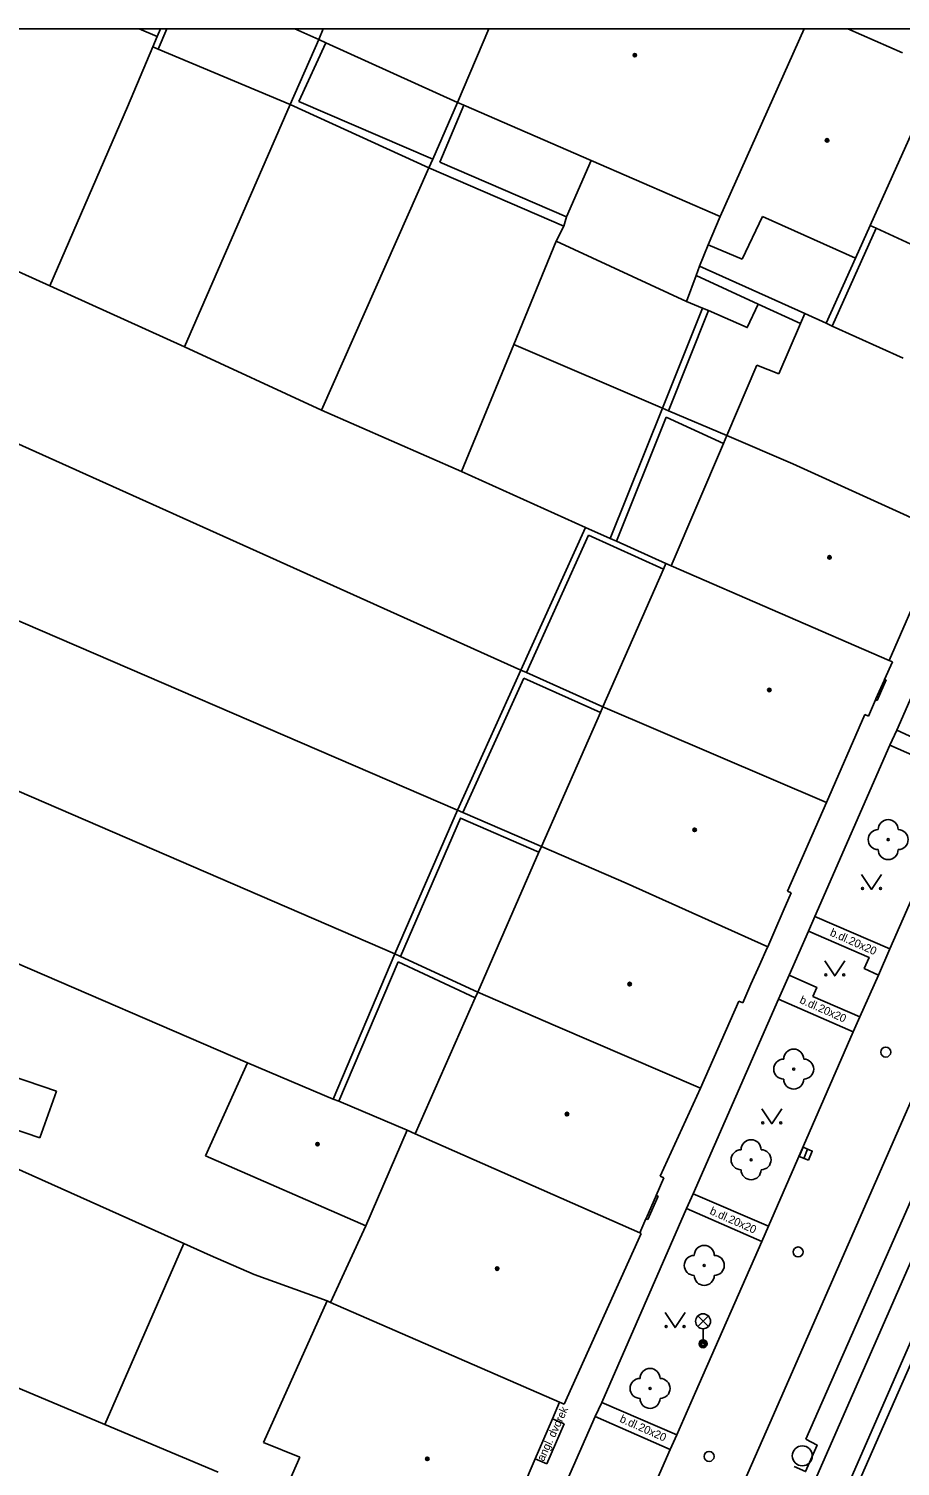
# Model space of a CAD drawing. Extents: x -596024 to -594475, y -1163820 to -1161957.
# Drawn here: x -595866.4 to -595822.8, y -1162028.7 to -1161956.9 of the extents above; entities that cross this region are included whole.
import ezdxf

# ---------------------------------------------------------------- set-up
doc = ezdxf.new("R2010")
doc.units = 0
for name, color, linetype in [('Level 10', 7, 'Continuous'), ('Level 11', 7, 'Continuous'), ('Level 22', 7, 'Continuous'), ('Level 27', 7, 'Continuous'), ('Level 28', 7, 'Continuous'), ('Level 33', 7, 'Continuous'), ('Level 36', 7, 'Continuous'), ('Level 39', 7, 'Continuous'), ('Level 40', 7, 'Continuous'), ('Level 42', 7, 'Continuous'), ('Level 5', 7, 'Continuous'), ('Level 6', 7, 'Continuous'), ('Level 7', 7, 'Continuous'), ('Vrstva 63', 7, 'Continuous')]:
    doc.layers.add(name, color=color, linetype=linetype)

msp = doc.modelspace()

# ---------------------------------------------------------------- linework, layer by layer
at = {"layer": 'Level 10'}
for points in [[(-595827.55, -1162027.38), (-595822.74, -1162016.44), (-595822.32, -1162015.5), (-595821.06, -1162012.53), (-595820.65, -1162011.59), (-595819.32, -1162008.66), (-595812.27, -1161992.6), (-595811.83, -1161991.6), (-595810.16, -1161987.8), (-595809.22, -1161985.63)], [(-595819.61, -1161994.34), (-595823.36, -1162002.87)], [(-595823.36, -1162002.87), (-595823.93, -1162004.18), (-595824.85, -1162006.27), (-595825.18, -1162007.02), (-595829.42, -1162016.73), (-595829.76, -1162017.5), (-595833.06, -1162025.03), (-595834, -1162027.16), (-595834.33, -1162027.9), (-595837.45, -1162035.01), (-595837.74, -1162035.66), (-595839.93, -1162040.66), (-595840.25, -1162041.39), (-595842.76, -1162047.12)], [(-595827.55, -1162027.38), (-595826.99, -1162027.67), (-595827.57, -1162029), (-595828.14, -1162028.75)]]:
    msp.add_lwpolyline(points, dxfattribs=at)
at = {"layer": 'Level 11'}
for p, q in [((-595860.866, -1161956.88), (-595859.97, -1161957.27)), ((-595859.491, -1161956.88), (-595859.93, -1161957.9))]:
    msp.add_line(p, q, dxfattribs=at)
for points in [[(-595859.97, -1161957.27), (-595860.19, -1161957.79)], [(-595859.81, -1161956.88), (-595859.97, -1161957.27)], [(-595851.9, -1161957.42), (-595853.33, -1161960.67)], [(-595860.19, -1161957.79), (-595861.45, -1161960.79), (-595865.34, -1161969.73)], [(-595859.93, -1161957.9), (-595860.19, -1161957.79)], [(-595853.33, -1161960.67), (-595859.93, -1161957.9)], [(-595852.89, -1161960.51), (-595851.54, -1161957.58)], [(-595853.33, -1161960.67), (-595858.6, -1161972.78)], [(-595846.39, -1161963.83), (-595853.33, -1161960.67)], [(-595852.89, -1161960.51), (-595846.2, -1161963.4)], [(-595844.97, -1161960.56), (-595846.2, -1161963.4)], [(-595845.85, -1161963.55), (-595844.65, -1161960.7)], [(-595846.39, -1161963.83), (-595851.76, -1161975.94)], [(-595846.2, -1161963.4), (-595846.39, -1161963.83)], [(-595839.65, -1161966.74), (-595846.39, -1161963.83)], [(-595845.85, -1161963.55), (-595839.52, -1161966.28)], [(-595838.28, -1161963.47), (-595839.52, -1161966.28)], [(-595872.5, -1161966.5), (-595865.34, -1161969.73)], [(-595840.03, -1161967.5), (-595839.65, -1161966.74)], [(-595839.52, -1161966.28), (-595839.65, -1161966.74)], [(-595840.03, -1161967.5), (-595842.15, -1161972.66)], [(-595833.51, -1161970.52), (-595840.03, -1161967.5)], [(-595826.23, -1161971.74), (-595824.04, -1161966.85)], [(-595832.44, -1161967.68), (-595832.87, -1161968.74)], [(-595832.87, -1161968.74), (-595833.04, -1161969.21)], [(-595832.87, -1161968.74), (-595827.61, -1161971.12)], [(-595825.07, -1161968.35), (-595826.54, -1161971.6)], [(-595833.04, -1161969.21), (-595833.51, -1161970.52)], [(-595833.04, -1161969.21), (-595829.93, -1161970.64)], [(-595865.34, -1161969.73), (-595858.6, -1161972.78)], [(-595849.54, -1162072.53), (-595845.35, -1162062.98), (-595836.61, -1162043.08), (-595829.36, -1162026.58), (-595821.11, -1162007.76), (-595812.02, -1161987.03), (-595805.18, -1161971.45), (-595804.77, -1161970.51)], [(-595832.72, -1161970.84), (-595834.71, -1161975.84)], [(-595832.42, -1161970.97), (-595834.41, -1161975.97)], [(-595833.51, -1161970.52), (-595832.72, -1161970.84)], [(-595832.72, -1161970.84), (-595832.42, -1161970.97)], [(-595829.93, -1161970.64), (-595830.48, -1161971.82), (-595832.42, -1161970.97)], [(-595827.82, -1161971.61), (-595829.93, -1161970.64)], [(-595858.6, -1161972.78), (-595851.76, -1161975.94)], [(-595842.15, -1161972.66), (-595844.76, -1161979.01)], [(-595842.15, -1161972.66), (-595834.71, -1161975.84)], [(-595871.23, -1161975.69), (-595841.79, -1161988.94)], [(-595851.76, -1161975.94), (-595844.76, -1161979.01)], [(-595834.71, -1161975.84), (-595837.33, -1161982.36)], [(-595834.71, -1161975.84), (-595834.41, -1161975.97)], [(-595834.41, -1161975.97), (-595831.5, -1161977.21)], [(-595834.54, -1161976.3), (-595837.01, -1161982.5)], [(-595831.67, -1161977.61), (-595834.54, -1161976.3)], [(-595844.76, -1161979.01), (-595838.56, -1161981.81)], [(-595838.56, -1161981.81), (-595841.79, -1161988.94)], [(-595837.33, -1161982.36), (-595838.56, -1161981.81)], [(-595841.52, -1161989.06), (-595838.41, -1161982.2)], [(-595838.41, -1161982.2), (-595834.67, -1161983.89)], [(-595837.01, -1161982.5), (-595837.33, -1161982.36)], [(-595834.55, -1161983.61), (-595837.01, -1161982.5)], [(-595819.42, -1161983.76), (-595823, -1161991.94)], [(-595844.96, -1161995.94), (-595870.08, -1161985.1)], [(-595841.79, -1161988.94), (-595844.96, -1161995.94)], [(-595841.52, -1161989.06), (-595841.79, -1161988.94)], [(-595837.7, -1161990.77), (-595841.52, -1161989.06)], [(-595844.69, -1161996.06), (-595841.64, -1161989.34)], [(-595841.64, -1161989.34), (-595837.82, -1161991.05)], [(-595823.99, -1161990.46), (-595823.54, -1161989.43)], [(-595823.62, -1161989.4), (-595823.54, -1161989.43)], [(-595824.07, -1161990.43), (-595823.99, -1161990.46)], [(-595823, -1161991.94), (-595823.35, -1161992.69)], [(-595819.31, -1161993.63), (-595823, -1161991.94)], [(-595823.35, -1161992.69), (-595827.1, -1162001.25)], [(-595819.61, -1161994.34), (-595823.35, -1161992.69)], [(-595868.96, -1161994.1), (-595848.09, -1162003.12)], [(-595844.96, -1161995.94), (-595848.09, -1162003.12)], [(-595844.96, -1161995.94), (-595844.69, -1161996.06)], [(-595844.69, -1161996.06), (-595840.77, -1161997.75)], [(-595847.81, -1162003.25), (-595844.81, -1161996.33), (-595840.89, -1161998.03)], [(-595827.1, -1162001.25), (-595827.42, -1162001.99)], [(-595823.36, -1162002.87), (-595827.1, -1162001.25)], [(-595827.42, -1162001.99), (-595828.38, -1162004.19)], [(-595823.93, -1162004.18), (-595824.63, -1162003.85), (-595824.39, -1162003.3), (-595827.42, -1162001.99)], [(-595867.81, -1162003.23), (-595855.45, -1162008.57)], [(-595848.09, -1162003.12), (-595851.17, -1162010.38)], [(-595847.81, -1162003.25), (-595848.09, -1162003.12)], [(-595843.95, -1162005.04), (-595847.81, -1162003.25)], [(-595850.9, -1162010.49), (-595847.93, -1162003.52)], [(-595844.08, -1162005.31), (-595847.93, -1162003.52)], [(-595828.38, -1162004.19), (-595828.92, -1162005.38)], [(-595828.38, -1162004.19), (-595827.01, -1162004.8), (-595827.21, -1162005.25)], [(-595828.92, -1162005.38), (-595833.19, -1162015.12)], [(-595828.92, -1162005.38), (-595825.18, -1162007.02)], [(-595824.85, -1162006.27), (-595827.21, -1162005.25)], [(-595869.47, -1162012.75), (-595858.64, -1162017.6)], [(-595835.45, -1162016.4), (-595834.93, -1162015.23)], [(-595835.03, -1162015.19), (-595834.93, -1162015.23)], [(-595833.19, -1162015.12), (-595833.52, -1162015.84)], [(-595833.19, -1162015.12), (-595829.42, -1162016.73)], [(-595833.52, -1162015.84), (-595837.75, -1162025.54)], [(-595835.55, -1162016.36), (-595835.45, -1162016.4)], [(-595833.52, -1162015.84), (-595829.76, -1162017.5)], [(-595821.19, -1162015.97), (-595821.22, -1162016.03), (-595821.26, -1162016.12), (-595826.41, -1162027.86)], [(-595858.64, -1162017.6), (-595862.59, -1162026.65)], [(-595855.13, -1162019.14), (-595857.31, -1162018.2), (-595858.64, -1162017.6)], [(-595855.13, -1162019.14), (-595851.47, -1162020.46)], [(-595862.59, -1162026.65), (-595871.26, -1162023)], [(-595838.08, -1162026.25), (-595837.75, -1162025.54)], [(-595837.75, -1162025.54), (-595834, -1162027.16)], [(-595838.08, -1162026.25), (-595841.21, -1162033.38)], [(-595840.22, -1162026.36), (-595839.63, -1162026.61)], [(-595838.08, -1162026.25), (-595834.33, -1162027.9)], [(-595856.93, -1162029.03), (-595862.59, -1162026.65)], [(-595840.5, -1162028.61), (-595839.63, -1162026.61)], [(-595826.41, -1162027.86), (-595833.62, -1162044.28)], [(-595841.08, -1162028.36), (-595840.5, -1162028.61)]]:
    msp.add_lwpolyline(points, dxfattribs=at)
at = {"layer": 'Level 22'}
for centre in [(-595823.44, -1161997.41), (-595828.16, -1162008.88), (-595830.29, -1162013.41), (-595832.63, -1162018.69), (-595835.34, -1162024.84)]:
    msp.add_circle(centre, 0.05, dxfattribs=at)
for centre, start, end in [((-595823.94, -1161997.41), 90, 270), ((-595823.44, -1161996.91), 0, 180), ((-595822.94, -1161997.41), 270, 90), ((-595823.44, -1161997.91), 180, 0), ((-595828.66, -1162008.88), 90, 270), ((-595828.16, -1162008.38), 0, 180), ((-595827.66, -1162008.88), 270, 90), ((-595828.16, -1162009.38), 180, 0), ((-595830.29, -1162012.91), 0, 180), ((-595830.79, -1162013.41), 90, 270), ((-595829.79, -1162013.41), 270, 90), ((-595830.29, -1162013.91), 180, 0), ((-595832.63, -1162018.19), 0, 180), ((-595833.13, -1162018.69), 90, 270), ((-595832.13, -1162018.69), 270, 90), ((-595832.63, -1162019.19), 180, 0), ((-595835.34, -1162024.34), 0, 180), ((-595835.84, -1162024.84), 90, 270), ((-595834.84, -1162024.84), 270, 90), ((-595835.34, -1162025.34), 180, 0)]:
    msp.add_arc(centre, 0.5, start, end, dxfattribs=at)
at = {"layer": 'Level 27'}
msp.add_line((-595827.657, -1162013.341), (-595827.463, -1162012.879), dxfattribs=at)
msp.add_lwpolyline([(-595827.426, -1162013.437), (-595827.233, -1162012.976), (-595827.694, -1162012.783), (-595827.887, -1162013.244)], close=True, dxfattribs=at)
msp.add_circle((-595827.73, -1162028.21), 0.5, dxfattribs=at)
at = {"layer": 'Level 28'}
for centre in [(-595823.56, -1162008.03), (-595827.94, -1162018.02), (-595832.39, -1162028.24)]:
    msp.add_circle(centre, 0.25, dxfattribs=at)
at = {"layer": 'Level 33'}
for p, q in [((-595832.955, -1162021.75), (-595832.425, -1162021.22)), ((-595832.955, -1162021.22), (-595832.425, -1162021.75)), ((-595832.69, -1162021.86), (-595832.69, -1162022.61))]:
    msp.add_line(p, q, dxfattribs=at)
for centre, radius in [((-595832.69, -1162021.485), 0.375), ((-595832.69, -1162022.61), 0.2), ((-595832.69, -1162022.61), 0.145), ((-595832.69, -1162022.61), 0.0876)]:
    msp.add_circle(centre, radius, dxfattribs=at)
at = {"layer": 'Level 36'}
for points in [[(-595824.77, -1161999.15), (-595824.27, -1161999.9), (-595823.77, -1161999.15)], [(-595826.61, -1162003.47), (-595826.11, -1162004.22), (-595825.61, -1162003.47)], [(-595829.76, -1162010.86), (-595829.26, -1162011.61), (-595828.76, -1162010.86)], [(-595834.59, -1162021.05), (-595834.09, -1162021.8), (-595833.59, -1162021.05)]]:
    msp.add_lwpolyline(points, dxfattribs=at)
for centre in [(-595824.72, -1161999.85), (-595823.821, -1161999.85), (-595826.56, -1162004.17), (-595825.661, -1162004.17), (-595829.71, -1162011.56), (-595828.811, -1162011.56), (-595834.54, -1162021.75), (-595833.641, -1162021.75)]:
    msp.add_circle(centre, 0.05, dxfattribs=at)
at = {"layer": 'Level 39'}
for centre, radius in [((-595836.1, -1161958.2), 0.09), ((-595836.1, -1161958.2), 0.0398), ((-595826.49, -1161962.46), 0.09), ((-595826.49, -1161962.46), 0.0398), ((-595826.37, -1161983.3), 0.09), ((-595826.37, -1161983.3), 0.0398), ((-595829.38, -1161989.93), 0.09), ((-595829.38, -1161989.93), 0.0398), ((-595833.11, -1161996.92), 0.09), ((-595833.11, -1161996.92), 0.0398), ((-595836.36, -1162004.63), 0.09), ((-595836.36, -1162004.63), 0.0398), ((-595839.49, -1162011.13), 0.09), ((-595839.49, -1162011.13), 0.0398), ((-595851.96, -1162012.63), 0.09), ((-595851.96, -1162012.63), 0.0398), ((-595842.98, -1162018.85), 0.09), ((-595842.98, -1162018.85), 0.0398), ((-595846.47, -1162028.36), 0.09), ((-595846.47, -1162028.36), 0.0398)]:
    msp.add_circle(centre, radius, dxfattribs=at)
at = {"layer": 'Level 5'}
for p, q in [((-595853.085, -1161956.88), (-595851.9, -1161957.42)), ((-595851.9, -1161957.42), (-595851.669, -1161956.88)), ((-595844.97, -1161960.56), (-595843.394, -1161956.88)), ((-595831.84, -1161966.27), (-595827.642, -1161956.88)), ((-595825.455, -1161956.88), (-595822.73, -1161958.09))]:
    msp.add_line(p, q, dxfattribs=at)
for points in [[(-595851.9, -1161957.42), (-595851.54, -1161957.58)], [(-595851.54, -1161957.58), (-595844.97, -1161960.56)], [(-595824.34, -1161966.71), (-595820.84, -1161958.93)], [(-595844.97, -1161960.56), (-595844.65, -1161960.7)], [(-595844.65, -1161960.7), (-595838.28, -1161963.47)], [(-595838.28, -1161963.47), (-595831.84, -1161966.27)], [(-595831.84, -1161966.27), (-595832.44, -1161967.68)], [(-595830.74, -1161968.39), (-595829.72, -1161966.27)], [(-595829.72, -1161966.27), (-595825.07, -1161968.35)], [(-595825.07, -1161968.35), (-595824.34, -1161966.71)], [(-595824.34, -1161966.71), (-595824.04, -1161966.85)], [(-595824.04, -1161966.85), (-595821.66, -1161967.95)], [(-595832.44, -1161967.68), (-595830.74, -1161968.39)], [(-595827.61, -1161971.12), (-595827.82, -1161971.61)], [(-595826.54, -1161971.6), (-595827.61, -1161971.12)], [(-595827.82, -1161971.61), (-595828.91, -1161974.12)], [(-595826.23, -1161971.74), (-595826.54, -1161971.6)], [(-595822.69, -1161973.34), (-595826.23, -1161971.74)], [(-595830, -1161973.7), (-595831.5, -1161977.21)], [(-595828.91, -1161974.12), (-595830, -1161973.7)], [(-595831.5, -1161977.21), (-595831.67, -1161977.61)], [(-595828.2, -1161978.63), (-595831.5, -1161977.21)], [(-595831.67, -1161977.61), (-595834.29, -1161983.73)], [(-595820.62, -1161982.08), (-595828.2, -1161978.63)], [(-595837.7, -1161990.77), (-595834.67, -1161983.89)], [(-595834.67, -1161983.89), (-595834.55, -1161983.61)], [(-595834.55, -1161983.61), (-595834.29, -1161983.73)], [(-595834.29, -1161983.73), (-595823.39, -1161988.45), (-595823.23, -1161988.52)], [(-595821.4, -1161983.88), (-595821.58, -1161984.29), (-595823.39, -1161988.45)], [(-595823.64, -1161989.45), (-595823.62, -1161989.4), (-595823.23, -1161988.52)], [(-595824.05, -1161990.38), (-595823.64, -1161989.45)], [(-595824.42, -1161991.24), (-595824.07, -1161990.43), (-595824.05, -1161990.38)], [(-595840.77, -1161997.75), (-595837.82, -1161991.05)], [(-595837.82, -1161991.05), (-595837.7, -1161990.77)], [(-595826.52, -1161995.56), (-595837.7, -1161990.77)], [(-595826.52, -1161995.56), (-595824.61, -1161991.16)], [(-595824.61, -1161991.16), (-595824.42, -1161991.24)], [(-595828.47, -1161999.99), (-595826.52, -1161995.56)], [(-595843.95, -1162005.04), (-595840.89, -1161998.03)], [(-595840.89, -1161998.03), (-595840.77, -1161997.75)], [(-595836.53, -1161999.59), (-595840.77, -1161997.75)], [(-595829.46, -1162002.76), (-595836.53, -1161999.59)], [(-595828.68, -1162000.98), (-595828.28, -1162000.07)], [(-595828.28, -1162000.07), (-595828.47, -1161999.99)], [(-595829.11, -1162001.96), (-595828.68, -1162000.98)], [(-595829.46, -1162002.76), (-595829.11, -1162001.96)], [(-595829.87, -1162003.68), (-595829.49, -1162002.82)], [(-595829.49, -1162002.82), (-595829.46, -1162002.76)], [(-595830.3, -1162004.63), (-595829.87, -1162003.68)], [(-595830.71, -1162005.56), (-595830.3, -1162004.63)], [(-595847.08, -1162012.11), (-595844.08, -1162005.31)], [(-595844.08, -1162005.31), (-595843.95, -1162005.04)], [(-595840.06, -1162006.72), (-595843.95, -1162005.04)], [(-595832.82, -1162009.83), (-595830.9, -1162005.48)], [(-595830.9, -1162005.48), (-595830.71, -1162005.56)], [(-595832.82, -1162009.83), (-595840.06, -1162006.72)], [(-595868.1, -1162008.94), (-595865.01, -1162009.98)], [(-595857.56, -1162013.22), (-595855.45, -1162008.57)], [(-595855.45, -1162008.57), (-595851.17, -1162010.38)], [(-595834.84, -1162014.23), (-595832.82, -1162009.83)], [(-595865.01, -1162009.98), (-595865.83, -1162012.32)], [(-595851.17, -1162010.38), (-595850.9, -1162010.49)], [(-595850.9, -1162010.49), (-595847.47, -1162011.94)], [(-595865.83, -1162012.32), (-595868.94, -1162011.27)], [(-595849.54, -1162016.72), (-595847.47, -1162011.94)], [(-595847.47, -1162011.94), (-595847.08, -1162012.11)], [(-595835.79, -1162017.09), (-595835.85, -1162017.06), (-595847.08, -1162012.11)], [(-595849.54, -1162016.72), (-595857.56, -1162013.22)], [(-595834.65, -1162014.31), (-595834.84, -1162014.23)], [(-595835.07, -1162015.28), (-595835.03, -1162015.19), (-595834.65, -1162014.31)], [(-595835.49, -1162016.23), (-595835.07, -1162015.28)], [(-595835.85, -1162017.06), (-595835.55, -1162016.36), (-595835.49, -1162016.23)], [(-595849.54, -1162016.72), (-595851.31, -1162020.54)], [(-595839.63, -1162025.63), (-595835.79, -1162017.09)], [(-595851.47, -1162020.46), (-595854.65, -1162027.55)], [(-595851.31, -1162020.54), (-595851.47, -1162020.46)], [(-595839.63, -1162025.63), (-595839.86, -1162025.53), (-595851.31, -1162020.54)], [(-595843.77, -1162034.57), (-595843.69, -1162034.39), (-595842.6, -1162031.86), (-595841.72, -1162029.84), (-595841.08, -1162028.36), (-595840.22, -1162026.36), (-595839.86, -1162025.53)], [(-595854.65, -1162027.55), (-595852.84, -1162028.28)], [(-595852.84, -1162028.28), (-595853.76, -1162030.36)]]:
    msp.add_lwpolyline(points, dxfattribs=at)
at = {"layer": 'Level 6'}
for points in [[(-595824.05, -1161990.38), (-595823.64, -1161989.45)], [(-595829.11, -1162001.96), (-595828.68, -1162000.98)], [(-595830.3, -1162004.63), (-595829.87, -1162003.68)], [(-595835.49, -1162016.23), (-595835.07, -1162015.28)]]:
    msp.add_lwpolyline(points, dxfattribs=at)
at = {"layer": 'Level 7'}
for points in [[(-595821.28, -1162020.13), (-595846.02, -1162076.71)], [(-595845.67, -1162076.71), (-595842.88, -1162070.36), (-595820.86, -1162020.31)]]:
    msp.add_lwpolyline(points, dxfattribs=at)
at = {"layer": 'Vrstva 63'}
msp.add_lwpolyline([(-594475.47, -1163820.23), (-596024.42, -1163820.23), (-596024.42, -1161956.88), (-594475.47, -1161956.88)], close=True, dxfattribs=at)

# ---------------------------------------------------------------- texts
at = {"layer": 'Level 40'}
for p in [(-595826.38, -1162002.19), (-595827.9, -1162005.56), (-595832.39, -1162016.11), (-595836.89, -1162026.5)]:
    msp.add_text('b.dl.20x20', height=0.4, rotation=336.01364, dxfattribs=at).set_placement(p)
at = {"layer": 'Level 42'}
msp.add_text('angl. dvorek', height=0.4, rotation=65.06794, dxfattribs=at).set_placement((-595840.65, -1162028.51))

doc.saveas('drawing.dxf')
